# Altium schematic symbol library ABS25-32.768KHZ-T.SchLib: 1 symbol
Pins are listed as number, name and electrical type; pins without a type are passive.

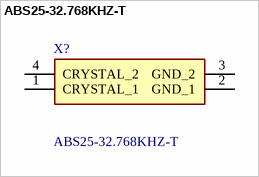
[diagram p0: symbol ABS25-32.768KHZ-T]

## ABS25-32.768KHZ-T
designator X?
ABRACON - ABS25-32.768KHZ-T - CRYSTAL, 32.768K, 12.5PF CL 8X2.5 SMD; Geometry.Height: 2.6mm
footprint ABS2532768KHZT
pins: 1 CRYSTAL_1, 2 GND_1, 3 GND_2, 4 CRYSTAL_2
